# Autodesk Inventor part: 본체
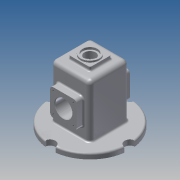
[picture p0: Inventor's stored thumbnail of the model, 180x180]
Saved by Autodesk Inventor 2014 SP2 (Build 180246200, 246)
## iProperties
Created: 2018-07
Part Number: 본체
Material: 알루미늄 6061
Document SubType Name: Modeling
Designer: cm
Density: 2.71 g/cm^3
Appearance: 알루미늄 - 평지
Mass: 912.757 g
Surface Area: 1017.53 cm^2
Volume: 336.811 cm^3
Author: cm
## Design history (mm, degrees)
sketch "스케치1"
  geometry: L1 (-37, -37)-(37, -37); L2 (37, -37)-(37, 37); L3 (37, 37)-(-37, 37); L4 (-37, 37)-(-37, -37); L5 (-37, -37)-(37, 37); L6 (37, -37)-(-37, 37); 1 further point
  constraints: 12 end point, 2 midpoint, 2 parallel, 1 horizontal, 1 perpendicular
  dimensions: "d0" = 74 distance of L3.end L2.end; "d1" = 74 distance of L2.end L1.end
extrude "돌출1" new body sketch "스케치1" distance "d2" = 110; taper "d3" = 0 deg
feature "쉘1" dims "d5" = 5
sketch "스케치3"
  geometry: L1 (-37, -37)-(37, -37) reference; L2 (-37, 37)-(-37, -37) reference; L3 (37, 37)-(-37, 37) reference; L4 (37, -37)-(37, 37) reference; L5 (-29, -37)-(29, -37); L6 (37, -29)-(37, 29); L7 (29, 37)-(-29, 37); L8 (-37, 29)-(-37, -29); L9 (-37, -37)-(37, 37); L10 (37, -37)-(-37, 37); C1 r 75 at (0, 0); A1 r 8 centre (-29, -29) between (-37, -29) and (-29, -37) reference; A2 r 8 centre (-29, 29) between (-29, 37) and (-37, 29) reference; A3 r 8 centre (29, 29) between (37, 29) and (29, 37) reference; A4 r 8 centre (29, -29) between (29, -37) and (37, -29) reference; A5 r 8 centre (29, -29) between (29, -37) and (37, -29); A6 r 8 centre (-29, -29) between (-37, -29) and (-29, -37); A7 r 8 centre (-29, 29) between (-29, 37) and (-37, 29); A8 r 8 centre (29, 29) between (37, 29) and (29, 37); 1 further point
  constraints: 12 end point, 8 point on circle, 8 point on line, 8 tangent, 5 centre point, 3 equal radius, 2 midpoint, 2 parallel, 1 coincident, 1 horizontal, 1 perpendicular
  dimensions: "d9" = 150 diameter of C1; "d10" = 74 distance of L2.start L3.start; "d11" = 74 distance of L3.start L1.end; "d12" = 8 radius of A5
extrude "돌출3" join sketch "스케치3" distance "d13" = 10; taper "d14" = 0 deg
sketch "스케치4"
  geometry: L1 (0, 0)-(0, 55); L2 (-29, 105)-(29, 105) reference; L3 (-32, 0)-(-32, 102) reference; L4 (32, 102)-(32, 0) reference; L5 (0, 55)-(-49.301, 55); L6 (-32, 80)-(-25, 77.452); L7 (-25, 77.452)-(-25, 55); L8 (-32, 80)-(-32, 55); A1 r 3 centre (-29, 102) between (-29, 105) and (-32, 102) reference; A2 r 3 centre (29, 102) between (32, 102) and (29, 105) reference
  constraints: 10 end point, 4 point on line, 2 perpendicular, 1 vertical
  dimensions: "d15" = 55 distance of L1.start L1.end; "d16" = 7 distance between parallel lines of L7 L3; "d17" = 50 diameter of L6.start L5; "d18" = 110 deg angle of L6 L3
revolve "회전1" sketch "스케치4" stored, may be unused: angle "d19" = 90 deg
fillet "모깎기2" dims "d20" = 8
fillet "모깎기3" dims "d21" = 3
sketch "스케치6"
  geometry: L1 (0, 92)-(58, 92) reference; L2 (29, -10)-(29, 45); L3 (4, 70)-(54, 70); L4 (54, 70)-(54, 20); L5 (54, 20)-(4, 20); L6 (4, 20)-(4, 70); L7 (4, 70)-(54, 20); L8 (54, 70)-(4, 20)
  constraints: 14 end point, 2 midpoint, 2 parallel, 2 perpendicular, 1 horizontal
  dimensions: "d22" = 55 distance of L2.start L2.end; "d23" = 50 distance of L4.end L5.end; "d24" = 50 distance of L3.end L4.end
extrude "돌출4" join sketch "스케치6" distance "d25" = 13; taper "d26" = 0 deg
sketch "스케치7"
  geometry: L1 (54, 20)-(54, 70) reference; L2 (29, -10)-(29, 45); C1 r 16 at (29, 45)
  constraints: 2 end point, 1 centre point, 1 coincident, 1 parallel
  dimensions: "d27" = 55 distance of L2.start L2.end; "d28" = 32 diameter of C1
extrude "돌출5" cut sketch "스케치7" stored distance "d29" = 13; taper "d30" = 0 deg
sketch "스케치8"
  geometry: L1 (-20, 20)-(20, 20); L2 (20, 20)-(20, -20); L3 (20, -20)-(-20, -20); L4 (-20, -20)-(-20, 20); L5 (-20, 20)-(20, -20); L6 (20, 20)-(-20, -20); 1 further point
  constraints: 12 end point, 2 midpoint, 2 parallel, 1 horizontal, 1 perpendicular
  dimensions: "d31" = 40 distance of L2.end L3.end; "d32" = 40 distance of L1.end L2.end
extrude "돌출6" join sketch "스케치8" distance "d33" = 7; taper "d34" = 0 deg
sketch "스케치9"
  geometry: C1 r 17.5 at (0, 0); 1 further point
  constraints: 1 centre point, 1 coincident
  dimensions: "d35" = 35 diameter of C1
extrude "돌출7" join sketch "스케치9" distance "d36" = 3; taper "d37" = 0 deg
sketch "스케치10"
  geometry: C1 r 17.5 at (0, 0) reference; 1 further point
  constraints: 1 coincident
hole "구멍1" sketch "스케치10" at (0, 0) diameter "d38" = 21; stored, may be unused: countersink angle "d42" = 90 deg, drill point angle "d44" = 118 deg; dims "d39" = 6, "d40" = 28, "d41" = 4, "d43" = 8
fillet "모깎기4" dims "d45" = 6
fillet "모깎기5" dims "d46" = 3
fillet "모깎기6" dims "d47" = 6
fillet "모깎기7" dims "d48" = 3
sketch "스케치11"
  geometry: A1 r 6 centre (10, 26) between (4, 26) and (10, 20) reference; A2 r 6 centre (48, 26) between (48, 20) and (54, 26) reference; A3 r 6 centre (48, 64) between (54, 64) and (48, 70) reference; A4 r 6 centre (10, 64) between (10, 70) and (4, 64) reference; 5 further points
  constraints: 4 coincident
hole "구멍2" sketch "스케치11" at (10, 64), (48, 64), (48, 26), (10, 26) diameter "d49" = 3.242; stored, may be unused: countersink angle "d53" = 90 deg, drill point angle "d55" = 118 deg; dims "d50" = 8, "d51" = 28, "d52" = 4, "d54" = 10
fillet "모깎기8" dims "d56" = 3
fillet "모깎기9" dims "d57" = 3
fillet "모깎기10" dims "d58" = 3
fillet "모깎기11" dims "d59" = 3
sketch "스케치12"
  geometry: L1 (29, 40)-(-29, 40) reference; L2 (0, -75)-(0, 75); L3 (-75, 0)-(75, 0); C1 r 72 at (0, 0) reference; C2 r 10 at (0, 75); C3 r 10 at (75, 0); C4 r 10 at (0, -75); C5 r 10 at (-75, 0); A1 r 75 centre (0, 0) between (0, -75) and (0, 75) reference; 1 further point
  constraints: 5 coincident, 4 centre point, 4 end point, 4 point on circle, 2 midpoint, 2 perpendicular
  dimensions: "d61" = 20 diameter of C2; "d62" = 20 diameter of C3; "d63" = 20 diameter of C4; "d64" = 20 diameter of C5
extrude "돌출8" cut sketch "스케치12" stored distance "d65" = 3; taper "d66" = 0 deg
chamfer "모따기1" distance "d67" = 1; stored, may be unused: second distance "d68" = 2, angle "d69" = 45 deg
sketch "스케치14"
  geometry: L1 (11.5, -18)-(46.5, -18) reference; L2 (19.022, 102)-(38.978, 102) reference; 3 further points
  constraints: 1 midpoint, 1 vertical alignment, 1 other
  dimensions: "d70" = 30 distance from line of point (29, 12) L1
feature "엠보싱1" sketch "스케치14" dims "d0" = 74, "d1" = 74, "d10" = 74, "d71" = 0.5, "d72" = 0
node "솔리드1"
mirror "대칭1"
mirror "대칭2"
mirror "대칭3"
